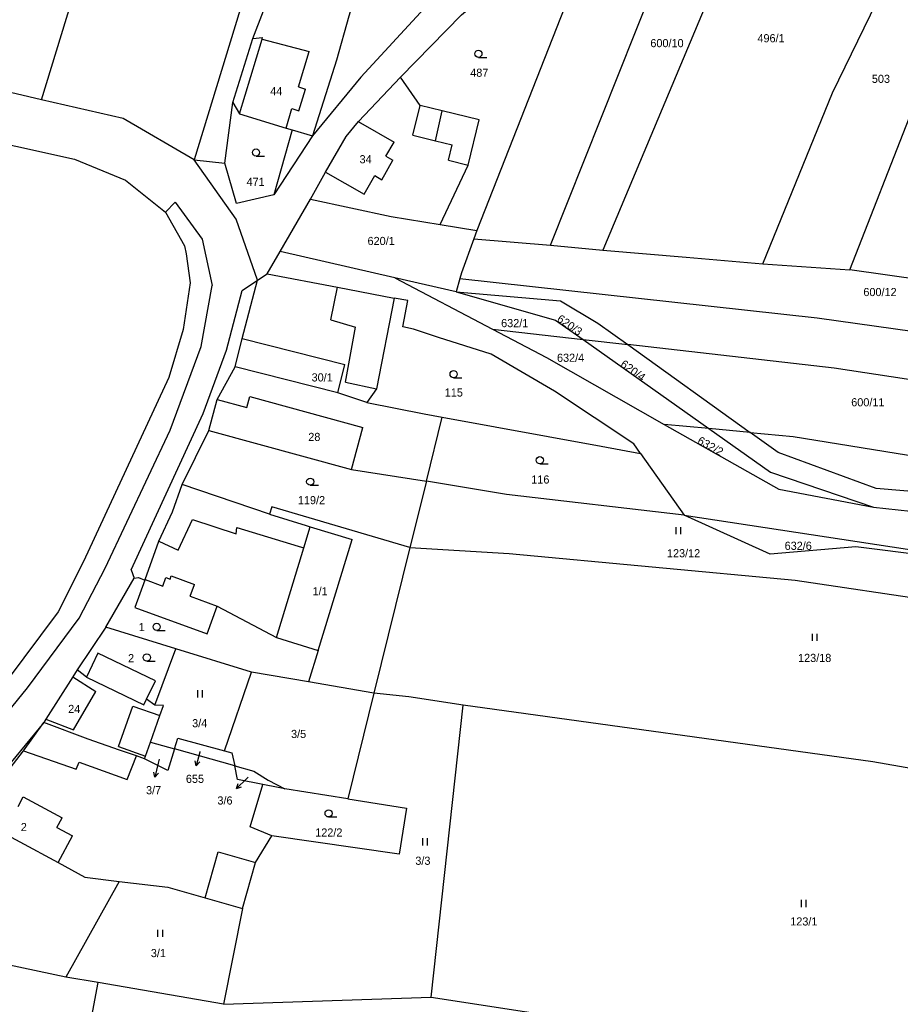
# Model space of a CAD drawing. Extents: x -744566 to -741843, y -1128407 to -1126744.
# Drawn here: x -742817.8 to -742633.6, y -1127345.9 to -1127139.9 of the extents above; entities that cross this region are included whole.
import ezdxf

# ---------------------------------------------------------------- set-up
doc = ezdxf.new("R2010")
doc.units = 0
for name, color, linetype in [('Hranice parcel', 7, 'Continuous'), ('Parcelní čísla', 7, 'Continuous'), ('Pop  PČ popisy', 7, 'Continuous'), ('Vnitřní kresba', 7, 'Continuous'), ('Značky kultur', 7, 'Continuous')]:
    doc.layers.add(name, color=color, linetype=linetype)

msp = doc.modelspace()

# ---------------------------------------------------------------- linework, layer by layer
at = {"layer": 'Hranice parcel'}
for p, q in [((-742734.68, -1127016.73), (-742781.25, -1127169.22)), ((-742694.65, -1127113.94), (-742722.13, -1127184.01)), ((-742813.25, -1127156.61), (-742828.27, -1127153.14)), ((-742774.85, -1127169.87), (-742773.17, -1127157.23)), ((-742756.51, -1127164.2), (-742764.59, -1127176.5)), ((-742781.25, -1127169.22), (-742774.85, -1127169.87)), ((-742763.32, -1127188.38), (-742756.98, -1127177.44)), ((-742729.83, -1127182.75), (-742722.13, -1127184.01)), ((-742722.13, -1127184.01), (-742722.77, -1127185.76)), ((-742722.77, -1127185.76), (-742706.71, -1127187.05)), ((-742706.71, -1127187.05), (-742695.82, -1127188.09)), ((-742766.04, -1127193.06), (-742763.32, -1127188.38)), ((-742739.28, -1127193.88), (-742763.32, -1127188.38)), ((-742662.31, -1127190.95), (-742644.1, -1127192.22)), ((-742768.06, -1127194.37), (-742766.04, -1127193.06)), ((-742566.48, -1127203.04), (-742644.1, -1127192.22)), ((-742726.46, -1127196.81), (-742739.28, -1127193.88)), ((-742739.28, -1127193.88), (-742718.84, -1127204.63)), ((-742725.69, -1127194.04), (-742726.46, -1127196.81)), ((-742726.46, -1127196.81), (-742704.64, -1127198.69)), ((-742718.84, -1127204.63), (-742699.9, -1127206.79)), ((-742699.9, -1127206.79), (-742690.57, -1127207.86)), ((-742699.9, -1127206.79), (-742673.62, -1127225.43)), ((-742690.57, -1127207.86), (-742664.96, -1127226.26)), ((-742732.7, -1127236.41), (-742729.39, -1127223.02)), ((-742729.39, -1127223.02), (-742696.14, -1127229.14)), ((-742783.76, -1127237.1), (-742778.23, -1127225.83)), ((-742673.62, -1127225.43), (-742682.93, -1127224.54)), ((-742664.96, -1127226.26), (-742673.62, -1127225.43)), ((-742696.14, -1127229.14), (-742687.9, -1127230.66)), ((-742687.9, -1127230.66), (-742678.76, -1127243.56)), ((-742732.7, -1127236.41), (-742736.14, -1127250.3)), ((-742639.2, -1127241.9), (-742621.56, -1127243.8)), ((-742678.76, -1127243.56), (-742598.97, -1127255.65)), ((-742736.14, -1127250.3), (-742743.69, -1127280.81)), ((-742799.73, -1127266.98), (-742805.74, -1127275.9)), ((-742785.11, -1127271.49), (-742799.73, -1127266.98)), ((-742789.51, -1127283.3), (-742785.11, -1127271.49)), ((-742769.26, -1127276.37), (-742785.11, -1127271.49)), ((-742774.96, -1127292.87), (-742769.26, -1127276.37)), ((-742757.36, -1127278.44), (-742769.26, -1127276.37)), ((-742743.69, -1127280.81), (-742757.36, -1127278.44)), ((-742743.69, -1127280.81), (-742749.15, -1127302.87)), ((-742736.37, -1127281.56), (-742743.69, -1127280.81)), ((-742725.03, -1127283.28), (-742736.37, -1127281.56)), ((-742731.72, -1127344.4), (-742725.03, -1127283.28)), ((-742790.45, -1127291.06), (-742785.38, -1127292.47)), ((-742772.81, -1127295.97), (-742785.38, -1127292.47)), ((-742749.15, -1127302.87), (-742762.29, -1127300.78)), ((-742796.97, -1127320.16), (-742808.12, -1127340.19)), ((-742771.16, -1127325.84), (-742775.15, -1127345.88)), ((-742809.96, -1127387.12), (-742801.38, -1127341.35)), ((-742801.38, -1127341.35), (-742808.12, -1127340.19)), ((-742775.15, -1127345.88), (-742801.38, -1127341.35)), ((-742775.15, -1127345.88), (-742731.72, -1127344.4))]:
    msp.add_line(p, q, dxfattribs=at)
for points in [[(-742813.25, -1127156.61), (-742778.25, -1127042.21), (-742763.25, -1126998.63), (-742748.81, -1126966.24)], [(-742656.1, -1127095.61), (-742668.92, -1127124.1), (-742695.82, -1127188.09)], [(-742706.71, -1127187.05), (-742685.41, -1127133.42), (-742671.65, -1127102.1)], [(-742662.31, -1127190.95), (-742647.78, -1127155.16), (-742629.16, -1127116.92), (-742619.79, -1127101.89)], [(-742644.1, -1127192.22), (-742631.06, -1127158.9), (-742603.37, -1127102.87)], [(-742738.13, -1127151.87), (-742725.34, -1127138.85), (-742706.66, -1127123.2), (-742694.65, -1127113.94)], [(-742773.17, -1127157.23), (-742769.01, -1127143.81), (-742766.77, -1127137.99), (-742764.69, -1127131.41), (-742763.33, -1127127.12)], [(-742746.73, -1127131.84), (-742748.92, -1127139.17), (-742751.52, -1127148.31), (-742756.51, -1127164.2)], [(-742731.14, -1127135.75), (-742733.12, -1127137.46), (-742746.45, -1127151.91), (-742756.51, -1127164.2)], [(-742756.98, -1127177.44), (-742753.8, -1127171.75), (-742749.51, -1127164.33), (-742746.92, -1127161.19), (-742738.13, -1127151.87)], [(-742729.83, -1127182.75), (-742723.99, -1127170.28), (-742721.67, -1127160.86), (-742729.37, -1127158.96), (-742734.01, -1127157.82), (-742738.13, -1127151.87)], [(-742781.25, -1127169.22), (-742796.14, -1127160.57), (-742813.25, -1127156.61)], [(-742773.17, -1127157.23), (-742771.82, -1127159.58), (-742762.06, -1127162.55), (-742760.77, -1127162.93), (-742764.59, -1127176.5)], [(-742830.93, -1127163.61), (-742806.35, -1127169.04), (-742795.67, -1127173.47), (-742787.26, -1127180.14), (-742783.29, -1127187.16), (-742782.95, -1127188.88), (-742782.14, -1127194.94), (-742783.62, -1127204.69), (-742786.61, -1127214.77), (-742804.45, -1127253.23), (-742809.73, -1127263.8), (-742820.62, -1127278.32)], [(-742768.06, -1127194.37), (-742772.5, -1127181.64), (-742781.25, -1127169.22)], [(-742764.59, -1127176.5), (-742772.44, -1127178.33), (-742774.85, -1127169.87)], [(-742756.98, -1127177.44), (-742740.1, -1127181.07), (-742729.83, -1127182.75)], [(-742722.77, -1127185.76), (-742725.36, -1127192.86), (-742725.69, -1127194.04)], [(-742695.82, -1127188.09), (-742678.35, -1127189.57), (-742662.31, -1127190.95)], [(-742766.04, -1127193.06), (-742751.29, -1127195.85), (-742739.47, -1127198.11)], [(-742772.74, -1127212.53), (-742771.21, -1127206.56), (-742768.06, -1127194.37)], [(-742725.69, -1127194.04), (-742650.94, -1127202.29), (-742606.23, -1127208.56), (-742569.32, -1127215.09)], [(-742726.46, -1127196.81), (-742705.66, -1127202.71), (-742699.9, -1127206.79)], [(-742739.47, -1127198.11), (-742743.16, -1127217.09), (-742745.13, -1127219.95)], [(-742737.64, -1127204.11), (-742736.58, -1127198.66), (-742739.47, -1127198.11)], [(-742704.64, -1127198.69), (-742696.83, -1127203.36), (-742690.57, -1127207.86)], [(-742719.13, -1127209.84), (-742730.16, -1127206.35), (-742735.37, -1127204.64), (-742737.64, -1127204.11)], [(-742718.84, -1127204.63), (-742707.57, -1127210.55), (-742682.93, -1127224.54)], [(-742572.17, -1127226.73), (-742608.43, -1127218.73), (-742647.39, -1127212.79), (-742690.57, -1127207.86)], [(-742687.9, -1127230.66), (-742689.33, -1127228.64), (-742705.92, -1127217.63), (-742719.13, -1127209.84)], [(-742778.23, -1127225.83), (-742776.45, -1127219.31), (-742772.74, -1127212.53)], [(-742745.13, -1127219.95), (-742751.2, -1127217.94), (-742772.74, -1127212.53)], [(-742745.13, -1127219.95), (-742733.19, -1127222.32), (-742729.39, -1127223.02)], [(-742778.23, -1127225.83), (-742748.39, -1127234), (-742732.7, -1127236.41)], [(-742682.93, -1127224.54), (-742658.99, -1127238.12), (-742639.2, -1127241.9)], [(-742673.62, -1127225.43), (-742660.72, -1127234.58), (-742639.2, -1127241.9)], [(-742664.96, -1127226.26), (-742655.98, -1127227.12), (-742608.13, -1127234.85), (-742577.19, -1127240.89)], [(-742577.19, -1127240.89), (-742621.26, -1127239.44), (-742638.6, -1127238), (-742659.14, -1127230.44), (-742664.96, -1127226.26)], [(-742678.76, -1127243.56), (-742715.93, -1127239.23), (-742732.7, -1127236.41)], [(-742791.59, -1127257.13), (-742791.56, -1127257.04), (-742788.68, -1127248.97), (-742785.8, -1127242.82), (-742783.76, -1127237.1)], [(-742736.14, -1127250.3), (-742765.02, -1127241.79), (-742765.5, -1127243.32), (-742783.76, -1127237.1)], [(-742598.97, -1127255.65), (-742642.9, -1127250.2), (-742660.81, -1127251.7), (-742678.76, -1127243.56)], [(-742736.14, -1127250.3), (-742715.39, -1127251.55), (-742655.59, -1127257.18), (-742597.39, -1127265.81), (-742577.59, -1127269.9)], [(-742799.73, -1127266.98), (-742793.82, -1127256.75), (-742792.94, -1127256.6), (-742791.59, -1127257.13)], [(-742791.59, -1127257.13), (-742793.68, -1127262.86), (-742778.58, -1127268.39), (-742776.45, -1127262.56), (-742764.09, -1127269.15), (-742755.34, -1127271.83), (-742757.36, -1127278.44)], [(-742789.51, -1127283.3), (-742791.23, -1127282.07), (-742789.37, -1127278.2), (-742801.41, -1127272.41), (-742803.83, -1127277.46), (-742805.74, -1127275.9)], [(-742805.74, -1127275.9), (-742806.68, -1127277.37), (-742812.31, -1127286.21), (-742812.76, -1127286.93)], [(-742790.45, -1127291.06), (-742788.48, -1127285.47), (-742787.73, -1127283.35), (-742789.51, -1127283.3)], [(-742583.12, -1127305.02), (-742639.33, -1127295.15), (-742725.03, -1127283.28)], [(-742812.76, -1127286.93), (-742822.58, -1127298.79), (-742825.03, -1127301.3)], [(-742791.67, -1127294.54), (-742793.35, -1127293.9), (-742796.91, -1127292.72), (-742803.47, -1127290.41), (-742812.76, -1127286.93)], [(-742791.67, -1127294.54), (-742791.47, -1127293.96), (-742790.45, -1127291.06)], [(-742785.38, -1127292.47), (-742784.67, -1127290.21), (-742774.96, -1127292.87)], [(-742785.38, -1127292.47), (-742786.8, -1127296.94), (-742791.67, -1127294.54)], [(-742774.96, -1127292.87), (-742773.39, -1127293.3), (-742772.81, -1127295.97)], [(-742772.81, -1127295.97), (-742768.78, -1127297.1), (-742765.8, -1127299.02), (-742762.29, -1127300.78)], [(-742766.91, -1127299.92), (-742772.19, -1127298.87), (-742772.81, -1127295.97)], [(-742765.04, -1127310.66), (-742769.57, -1127308.75), (-742766.91, -1127299.92)], [(-742762.29, -1127300.78), (-742763.69, -1127300.56), (-742766.91, -1127299.92)], [(-742825.03, -1127301.3), (-742822.92, -1127302.22), (-742825.81, -1127307.59), (-742809.73, -1127316.24), (-742804.13, -1127319.29), (-742796.97, -1127320.16)], [(-742749.15, -1127302.87), (-742736.87, -1127304.83), (-742738.41, -1127314.45), (-742765.04, -1127310.66)], [(-742771.16, -1127325.84), (-742768.44, -1127316.21), (-742765.04, -1127310.66)], [(-742796.97, -1127320.16), (-742786.76, -1127321.38), (-742778.95, -1127323.64), (-742771.16, -1127325.84)], [(-742808.12, -1127340.19), (-742832.48, -1127335.04), (-742837.98, -1127333.31), (-742850.51, -1127328.29)], [(-742731.72, -1127344.4), (-742692.68, -1127350.41), (-742637.04, -1127361.12)]]:
    msp.add_lwpolyline(points, dxfattribs=at)
at = {"layer": 'Pop  PČ popisy'}
for p, q in [((-742780.13, -1127293.1), (-742780.856, -1127296.012)), ((-742780.11, -1127292.99), (-742780.13, -1127293.1)), ((-742788.81, -1127295.45), (-742789.485, -1127298.374)), ((-742788.62, -1127294.6), (-742788.81, -1127295.45)), ((-742780.856, -1127296.012), (-742781.1, -1127294.919)), ((-742780.856, -1127296.012), (-742780.128, -1127295.161)), ((-742789.485, -1127298.374), (-742789.748, -1127297.286)), ((-742789.485, -1127298.374), (-742788.772, -1127297.511)), ((-742770.29, -1127298.67), (-742772.449, -1127300.755)), ((-742772.449, -1127300.755), (-742772.076, -1127299.699)), ((-742769.98, -1127298.38), (-742770.29, -1127298.67)), ((-742772.449, -1127300.755), (-742771.38, -1127300.419))]:
    msp.add_line(p, q, dxfattribs=at)
at = {"layer": 'Vnitřní kresba'}
for p, q in [((-742769.01, -1127143.81), (-742766.96, -1127143.59)), ((-742767.06, -1127143.93), (-742766.96, -1127143.59)), ((-742771.82, -1127159.58), (-742767.06, -1127143.93)), ((-742767.06, -1127143.93), (-742757.2, -1127146.56)), ((-742759.44, -1127153.94), (-742757.2, -1127146.56)), ((-742759.44, -1127153.94), (-742758.01, -1127154.38)), ((-742759.39, -1127158.92), (-742758.01, -1127154.38)), ((-742735.55, -1127164.03), (-742734.01, -1127157.82)), ((-742762.06, -1127162.55), (-742760.82, -1127158.48)), ((-742760.82, -1127158.48), (-742759.39, -1127158.92)), ((-742730.82, -1127165.2), (-742729.37, -1127158.96)), ((-742746.92, -1127161.19), (-742746.49, -1127161.44)), ((-742746.49, -1127161.44), (-742739.46, -1127165.49)), ((-742760.77, -1127162.93), (-742756.51, -1127164.2)), ((-742735.55, -1127164.03), (-742730.82, -1127165.2)), ((-742741.16, -1127168.43), (-742739.46, -1127165.49)), ((-742730.82, -1127165.2), (-742727.31, -1127166.06)), ((-742728.1, -1127169.27), (-742727.31, -1127166.06)), ((-742741.16, -1127168.43), (-742739.69, -1127169.28)), ((-742742.03, -1127173.35), (-742739.69, -1127169.28)), ((-742728.1, -1127169.27), (-742723.99, -1127170.28)), ((-742753.8, -1127171.75), (-742745.75, -1127176.39)), ((-742745.75, -1127176.39), (-742743.5, -1127172.5)), ((-742743.5, -1127172.5), (-742742.03, -1127173.35)), ((-742787.26, -1127180.14), (-742785.27, -1127178.06)), ((-742785.27, -1127178.06), (-742779.59, -1127185.83)), ((-742779.59, -1127185.83), (-742777.49, -1127195.5)), ((-742771.22, -1127196.55), (-742768.06, -1127194.37)), ((-742779.83, -1127208.27), (-742777.49, -1127195.5)), ((-742774.52, -1127209.02), (-742771.22, -1127196.55)), ((-742752.68, -1127202.66), (-742751.29, -1127195.85)), ((-742752.68, -1127202.66), (-742747.52, -1127204.24)), ((-742749.65, -1127215.74), (-742747.52, -1127204.24)), ((-742771.21, -1127206.56), (-742749.8, -1127212.05)), ((-742786.33, -1127225.73), (-742779.83, -1127208.27)), ((-742779.4, -1127222.27), (-742774.52, -1127209.02)), ((-742751.2, -1127217.94), (-742749.8, -1127212.05)), ((-742749.65, -1127215.74), (-742743.16, -1127217.09)), ((-742776.45, -1127219.31), (-742770.25, -1127221)), ((-742770.25, -1127221), (-742769.62, -1127218.71)), ((-742769.62, -1127218.71), (-742745.98, -1127225.18)), ((-742794.47, -1127254.98), (-742779.4, -1127222.27)), ((-742799.87, -1127254.66), (-742786.33, -1127225.73)), ((-742748.39, -1127234), (-742745.98, -1127225.18)), ((-742784.62, -1127250.9), (-742781.6, -1127244.46)), ((-742781.6, -1127244.46), (-742772.5, -1127247.48)), ((-742765.5, -1127243.32), (-742757.86, -1127245.7)), ((-742772.5, -1127247.48), (-742772.35, -1127246.12)), ((-742772.35, -1127246.12), (-742759.55, -1127250.04)), ((-742758.36, -1127250.41), (-742757, -1127245.96)), ((-742757.86, -1127245.7), (-742757, -1127245.96)), ((-742757, -1127245.96), (-742748.25, -1127248.63)), ((-742755.34, -1127271.83), (-742748.25, -1127248.63)), ((-742788.68, -1127248.97), (-742784.62, -1127250.9)), ((-742764.09, -1127269.15), (-742758.36, -1127250.41)), ((-742759.55, -1127250.04), (-742758.36, -1127250.41)), ((-742805.34, -1127265.1), (-742799.87, -1127254.66)), ((-742794.47, -1127254.98), (-742793.82, -1127256.75)), ((-742791.56, -1127257.04), (-742787.87, -1127258.39)), ((-742787.87, -1127258.39), (-742787.22, -1127256.6)), ((-742787.22, -1127256.6), (-742786.32, -1127256.93)), ((-742786.32, -1127256.93), (-742786.08, -1127256.25)), ((-742786.08, -1127256.25), (-742781.24, -1127258.02)), ((-742782.14, -1127260.48), (-742781.24, -1127258.02)), ((-742782.14, -1127260.48), (-742776.45, -1127262.56)), ((-742816.12, -1127279.67), (-742805.34, -1127265.1)), ((-742806.68, -1127277.37), (-742801.85, -1127280.44)), ((-742803.83, -1127277.46), (-742791.8, -1127283.24)), ((-742828.54, -1127294.89), (-742816.12, -1127279.67)), ((-742806.5, -1127288.47), (-742801.85, -1127280.44)), ((-742797.08, -1127291.98), (-742794.09, -1127283.5)), ((-742794.09, -1127283.5), (-742788.48, -1127285.47)), ((-742791.8, -1127283.24), (-742791.23, -1127282.07)), ((-742817.01, -1127292.85), (-742812.76, -1127286.93)), ((-742812.31, -1127286.21), (-742806.5, -1127288.47)), ((-742797.08, -1127291.98), (-742791.47, -1127293.96)), ((-742821.15, -1127298.28), (-742817.01, -1127292.85)), ((-742817.01, -1127292.85), (-742805.94, -1127296.71)), ((-742795.29, -1127298.83), (-742793.35, -1127293.9)), ((-742805.94, -1127296.71), (-742805.36, -1127295.2)), ((-742805.36, -1127295.2), (-742795.29, -1127298.83)), ((-742818.13, -1127304.52), (-742817.03, -1127302.49)), ((-742817.03, -1127302.49), (-742808.92, -1127306.85)), ((-742810.01, -1127308.88), (-742808.92, -1127306.85)), ((-742810.01, -1127308.88), (-742806.73, -1127310.65)), ((-742809.73, -1127316.24), (-742806.73, -1127310.65)), ((-742778.95, -1127323.64), (-742776.23, -1127314.01)), ((-742776.23, -1127314.01), (-742768.44, -1127316.21))]:
    msp.add_line(p, q, dxfattribs=at)
at = {"layer": 'Značky kultur'}
for p, q in [((-742721.823, -1127147.76), (-742720.073, -1127147.76)), ((-742768.343, -1127168.4), (-742766.593, -1127168.4)), ((-742727.013, -1127214.79), (-742725.263, -1127214.79)), ((-742708.973, -1127232.8), (-742707.223, -1127232.8)), ((-742757.003, -1127237.29), (-742755.253, -1127237.29)), ((-742680.471, -1127247.53), (-742680.471, -1127246.03)), ((-742679.47, -1127247.53), (-742679.47, -1127246.03)), ((-742789.123, -1127267.66), (-742787.373, -1127267.66)), ((-742651.931, -1127269.85), (-742651.931, -1127268.35)), ((-742650.93, -1127269.85), (-742650.93, -1127268.35)), ((-742791.193, -1127274.07), (-742789.443, -1127274.07)), ((-742780.511, -1127281.67), (-742780.511, -1127280.17)), ((-742779.51, -1127281.67), (-742779.51, -1127280.17)), ((-742753.163, -1127306.69), (-742751.413, -1127306.69)), ((-742733.481, -1127312.65), (-742733.481, -1127311.15)), ((-742732.48, -1127312.65), (-742732.48, -1127311.15)), ((-742654.251, -1127325.53), (-742654.251, -1127324.03)), ((-742653.25, -1127325.53), (-742653.25, -1127324.03)), ((-742788.861, -1127331.79), (-742788.861, -1127330.29)), ((-742787.86, -1127331.79), (-742787.86, -1127330.29))]:
    msp.add_line(p, q, dxfattribs=at)
for centre in [(-742721.823, -1127147.01), (-742768.343, -1127167.65), (-742727.013, -1127214.04), (-742708.973, -1127232.05), (-742757.003, -1127236.54), (-742789.123, -1127266.91), (-742791.193, -1127273.32), (-742753.163, -1127305.94)]:
    msp.add_circle(centre, 0.75, dxfattribs=at)

# ---------------------------------------------------------------- texts
at = {"layer": 'Parcelní čísla'}
for s, p in [('496/1', (-742663.45, -1127144.6)), ('600/10', (-742685.85, -1127145.63)), ('487', (-742723.534, -1127151.82)), ('503', (-742639.51, -1127153.1)), ('44', (-742765.382, -1127155.69)), ('34', (-742746.682, -1127169.92)), ('471', (-742770.324, -1127174.65)), ('620/1', (-742745.013, -1127187.02)), ('600/12', (-742641.29, -1127197.71)), ('632/1', (-742717.07, -1127204.21)), ('632/4', (-742705.38, -1127211.46)), ('30/1', (-742756.721, -1127215.57)), ('115', (-742728.864, -1127218.73)), ('600/11', (-742643.83, -1127220.77)), ('28', (-742757.412, -1127228.02)), ('116', (-742710.764, -1127236.93)), ('119/2', (-742759.583, -1127241.25)), ('123/12', (-742682.38, -1127252.36)), ('632/6', (-742657.76, -1127250.8)), ('1/1', (-742756.528, -1127260.32)), ('1', (-742792.88, -1127267.8)), ('2', (-742795.11, -1127274.31)), ('123/18', (-742654.95, -1127274.26)), ('24', (-742807.642, -1127284.94)), ('3/4', (-742781.708, -1127287.92)), ('3/5', (-742761.018, -1127290.17)), ('655', (-742783.014, -1127299.563)), ('3/7', (-742791.358, -1127301.943)), ('3/6', (-742776.417, -1127304.093)), ('2', (-742817.55, -1127309.65)), ('122/2', (-742755.963, -1127310.79)), ('3/3', (-742735.018, -1127316.7)), ('123/1', (-742656.59, -1127329.4)), ('3/1', (-742790.348, -1127336.02))]:
    msp.add_text(s, height=1.7, dxfattribs=at).set_placement(p)
for s, rotation, p in [('620/3', 325, (-742705.527, -1127202.836)), ('620/4', 324, (-742692.269, -1127212.297)), ('632/2', 331, (-742676.162, -1127228.453))]:
    msp.add_text(s, height=1.7, rotation=rotation, dxfattribs=at).set_placement(p)

doc.saveas('drawing.dxf')
